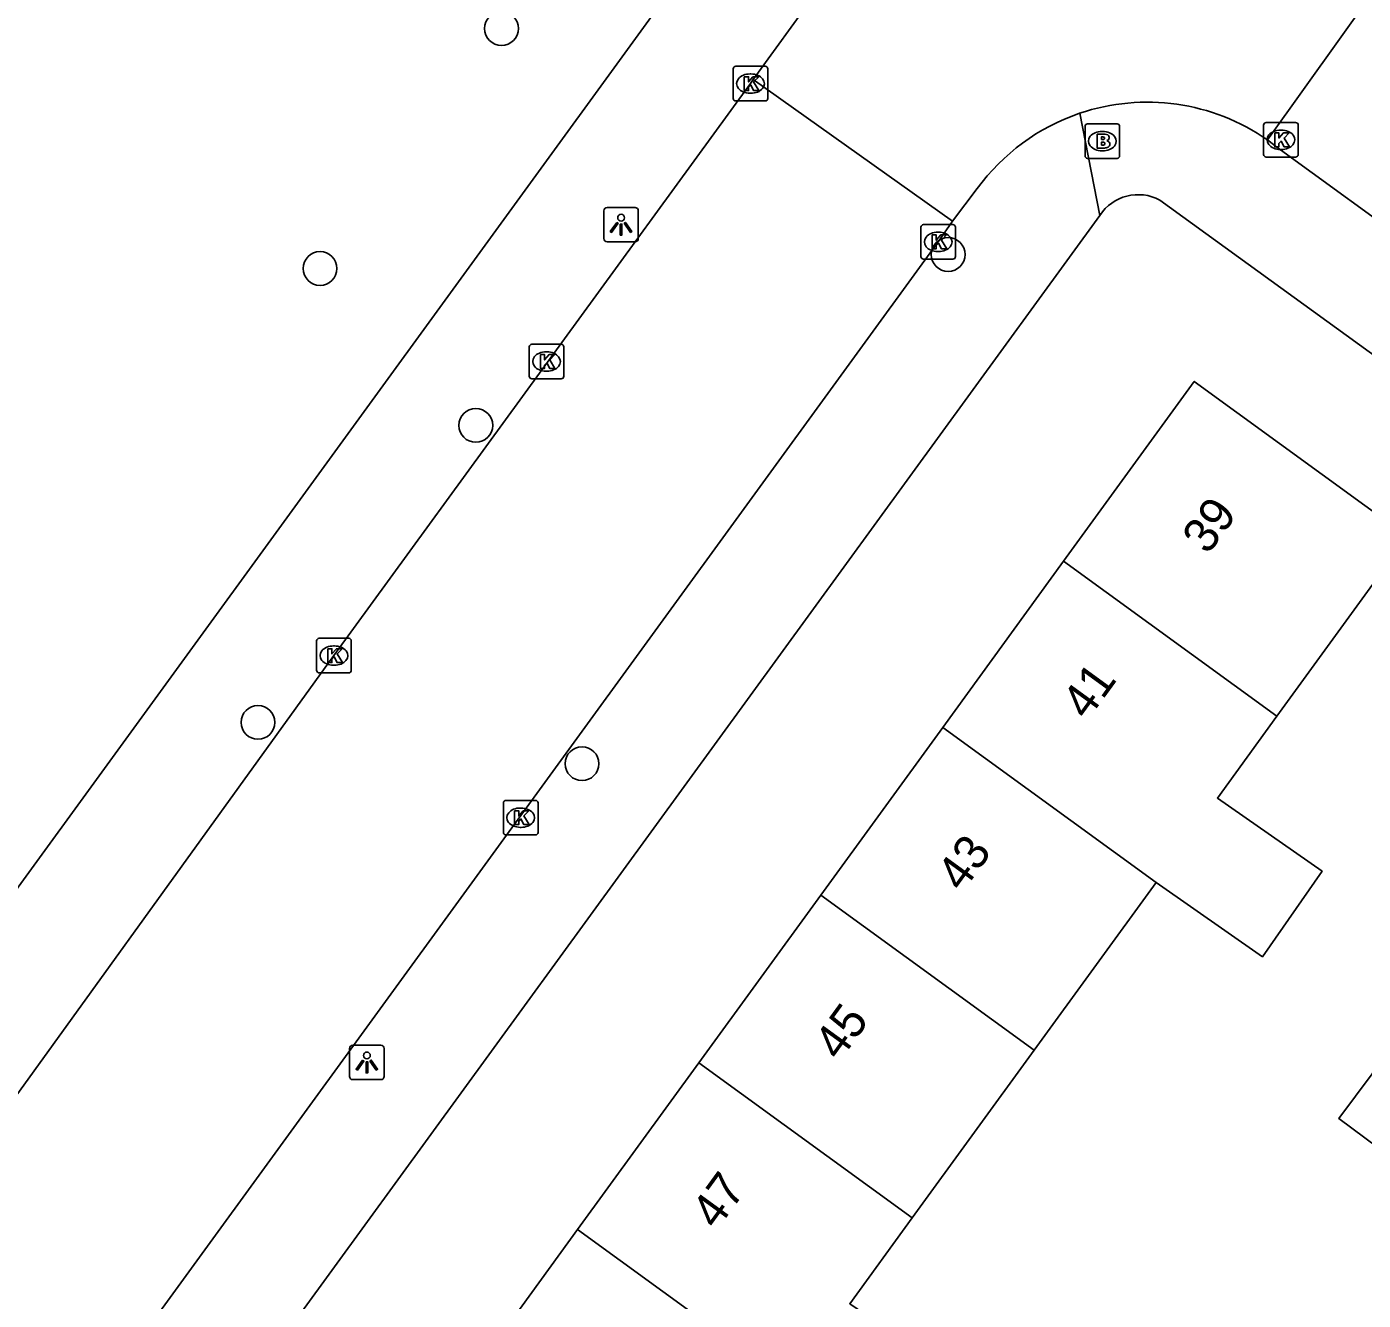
# Model space of a CAD drawing. Extents: x 159675 to 160530, y 382179 to 382901.
# Drawn here: x 160100.56 to 160139.21, y 382590.02 to 382626.86 of the extents above; entities that cross this region are included whole.
import ezdxf

# ---------------------------------------------------------------- set-up
doc = ezdxf.new("R2010")
doc.units = 0
for name, color, linetype in [('IMGEO_Boom', 7, 'Continuous'), ('IMGEO_Brandkraan', 7, 'Continuous'), ('IMGEO_Kolk', 7, 'Continuous'), ('IMGEO_Lichtpunt', 7, 'Continuous'), ('IMGEO_Pand', 7, 'Continuous'), ('IMGEO_Pand_nummerreeks', 7, 'Continuous'), ('IMGEO_Rijbaan_lokaal_open', 7, 'Continuous'), ('IMGEO_Voetpad_open', 7, 'Continuous')]:
    doc.layers.add(name, color=color, linetype=linetype)

msp = doc.modelspace()

# ---------------------------------------------------------------- linework, layer by layer
at = {"layer": 'IMGEO_Boom'}
for centre in [(160114.289, 382626.806), (160127.205, 382620.272), (160109.04, 382619.867), (160113.544, 382615.329), (160107.245, 382606.738), (160116.616, 382605.543)]:
    msp.add_circle(centre, 0.489, dxfattribs=at)
at = {"layer": 'IMGEO_Brandkraan'}
for p, q in [((160131.163, 382623.125), (160131.163, 382623.977)), ((160131.238, 382624.051), (160132.09, 382624.051)), ((160132.164, 382623.977), (160132.164, 382623.125)), ((160131.651, 382623.831), (160131.676, 382623.831)), ((160131.674, 382623.271), (160131.649, 382623.271)), ((160132.09, 382623.051), (160131.238, 382623.051))]:
    msp.add_line(p, q, dxfattribs=at)
for points in [[(160131.163, 382623.125), (160131.163, 382623.977)], [(160131.238, 382624.051), (160132.09, 382624.051)], [(160132.164, 382623.977), (160132.164, 382623.125)], [(160131.511, 382623.751), (160131.511, 382623.351), (160131.724, 382623.351)], [(160131.742, 382623.751), (160131.511, 382623.751)], [(160131.69, 382623.67), (160131.636, 382623.67), (160131.636, 382623.594)], [(160131.636, 382623.594), (160131.689, 382623.594)], [(160131.698, 382623.518), (160131.636, 382623.518), (160131.636, 382623.437)], [(160131.636, 382623.437), (160131.698, 382623.437)], [(160132.09, 382623.051), (160131.238, 382623.051)]]:
    msp.add_lwpolyline(points, dxfattribs=at)
for centre, radius, start, end in [((160131.24, 382623.975), 0.0765, 91.552, 178.448), ((160131.24, 382623.975), 0.0765, 91.552, 178.448), ((160132.088, 382623.975), 0.0765, 1.552, 88.448), ((160132.088, 382623.975), 0.0765, 1.552, 88.448), ((160131.691, 382623.632), 0.0379, 267.8285, 90.9355), ((160131.746, 382623.606), 0.145, 59.4692, 91.5367), ((160131.771, 382623.653), 0.0922, 285.5137, 58.1501), ((160131.699, 382623.477), 0.0404, 269.8759, 90.5077), ((160131.73, 382623.602), 0.251, 268.6676, 293.5347), ((160131.776, 382623.461), 0.105, 301.3115, 78.989), ((160131.24, 382623.127), 0.0765, 181.552, 268.448), ((160131.24, 382623.127), 0.0765, 181.552, 268.448), ((160132.088, 382623.127), 0.0765, 271.552, 358.448), ((160132.088, 382623.127), 0.0765, 271.552, 358.448)]:
    msp.add_arc(centre, radius, start, end, dxfattribs=at)
for centre, major_axis, ratio, start_param, end_param in [((160131.65, 382623.551), (-0.387, 0.002), 0.722429, 4.712389, 7.853982), ((160131.675, 382623.551), (-0.39, 0.002), 0.717154, 1.570796, 4.712389)]:
    msp.add_ellipse(centre, major_axis=major_axis, ratio=ratio, start_param=start_param, end_param=end_param, dxfattribs=at)
at = {"layer": 'IMGEO_Kolk'}
for p, q in [((160120.987, 382624.788), (160120.987, 382625.64)), ((160121.062, 382625.714), (160121.914, 382625.714)), ((160121.988, 382625.64), (160121.988, 382624.788)), ((160121.475, 382625.494), (160121.5, 382625.494)), ((160121.498, 382624.934), (160121.473, 382624.934)), ((160121.914, 382624.714), (160121.062, 382624.714)), ((160136.327, 382623.163), (160136.327, 382624.015)), ((160136.402, 382624.089), (160137.254, 382624.089)), ((160137.328, 382624.015), (160137.328, 382623.163)), ((160136.815, 382623.869), (160136.84, 382623.869)), ((160136.838, 382623.309), (160136.813, 382623.309)), ((160137.254, 382623.089), (160136.402, 382623.089)), ((160126.417, 382620.21), (160126.417, 382621.062)), ((160126.492, 382621.136), (160127.344, 382621.136)), ((160126.905, 382620.916), (160126.93, 382620.916)), ((160127.418, 382621.062), (160127.418, 382620.21)), ((160127.344, 382620.136), (160126.492, 382620.136)), ((160126.928, 382620.356), (160126.903, 382620.356)), ((160115.09, 382616.749), (160115.09, 382617.601)), ((160115.165, 382617.675), (160116.017, 382617.675)), ((160115.578, 382617.455), (160115.603, 382617.455)), ((160116.091, 382617.601), (160116.091, 382616.749)), ((160116.017, 382616.675), (160115.165, 382616.675)), ((160115.601, 382616.895), (160115.576, 382616.895)), ((160108.942, 382608.244), (160108.942, 382609.096)), ((160109.017, 382609.17), (160109.869, 382609.17)), ((160109.43, 382608.95), (160109.455, 382608.95)), ((160109.943, 382609.096), (160109.943, 382608.244)), ((160109.869, 382608.17), (160109.017, 382608.17)), ((160109.453, 382608.39), (160109.428, 382608.39)), ((160114.343, 382603.556), (160114.343, 382604.408)), ((160114.418, 382604.482), (160115.27, 382604.482)), ((160115.344, 382604.408), (160115.344, 382603.556)), ((160114.831, 382604.262), (160114.856, 382604.262)), ((160114.854, 382603.702), (160114.829, 382603.702)), ((160115.27, 382603.482), (160114.418, 382603.482))]:
    msp.add_line(p, q, dxfattribs=at)
for points in [[(160120.987, 382624.788), (160120.987, 382625.64)], [(160121.062, 382625.714), (160121.914, 382625.714)], [(160121.988, 382625.64), (160121.988, 382624.788)], [(160121.308, 382625.414), (160121.431, 382625.414), (160121.431, 382625.263), (160121.561, 382625.414), (160121.725, 382625.414), (160121.579, 382625.263), (160121.732, 382625.014), (160121.58, 382625.014), (160121.495, 382625.178), (160121.431, 382625.111), (160121.431, 382625.014), (160121.308, 382625.014), (160121.308, 382625.414)], [(160121.914, 382624.714), (160121.062, 382624.714)], [(160136.327, 382623.163), (160136.327, 382624.015)], [(160136.402, 382624.089), (160137.254, 382624.089)], [(160137.328, 382624.015), (160137.328, 382623.163)], [(160136.648, 382623.789), (160136.771, 382623.789), (160136.771, 382623.638), (160136.901, 382623.789), (160137.065, 382623.789), (160136.919, 382623.638), (160137.072, 382623.389), (160136.92, 382623.389), (160136.835, 382623.553), (160136.771, 382623.486), (160136.771, 382623.389), (160136.648, 382623.389), (160136.648, 382623.789)], [(160137.254, 382623.089), (160136.402, 382623.089)], [(160126.417, 382620.21), (160126.417, 382621.062)], [(160126.492, 382621.136), (160127.344, 382621.136)], [(160127.418, 382621.062), (160127.418, 382620.21)], [(160126.738, 382620.836), (160126.861, 382620.836), (160126.861, 382620.685), (160126.991, 382620.836), (160127.155, 382620.836), (160127.009, 382620.685), (160127.162, 382620.436), (160127.01, 382620.436), (160126.925, 382620.6), (160126.861, 382620.533), (160126.861, 382620.436), (160126.738, 382620.436), (160126.738, 382620.836)], [(160127.344, 382620.136), (160126.492, 382620.136)], [(160115.09, 382616.749), (160115.09, 382617.601)], [(160115.165, 382617.675), (160116.017, 382617.675)], [(160116.091, 382617.601), (160116.091, 382616.749)], [(160115.411, 382617.375), (160115.534, 382617.375), (160115.534, 382617.224), (160115.664, 382617.375), (160115.828, 382617.375), (160115.682, 382617.224), (160115.835, 382616.975), (160115.683, 382616.975), (160115.598, 382617.139), (160115.534, 382617.072), (160115.534, 382616.975), (160115.411, 382616.975), (160115.411, 382617.375)], [(160116.017, 382616.675), (160115.165, 382616.675)], [(160108.942, 382608.244), (160108.942, 382609.096)], [(160109.017, 382609.17), (160109.869, 382609.17)], [(160109.943, 382609.096), (160109.943, 382608.244)], [(160109.263, 382608.87), (160109.386, 382608.87), (160109.386, 382608.719), (160109.516, 382608.87), (160109.68, 382608.87), (160109.534, 382608.719), (160109.687, 382608.47), (160109.535, 382608.47), (160109.45, 382608.634), (160109.386, 382608.567), (160109.386, 382608.47), (160109.263, 382608.47), (160109.263, 382608.87)], [(160109.869, 382608.17), (160109.017, 382608.17)], [(160114.343, 382603.556), (160114.343, 382604.408)], [(160114.418, 382604.482), (160115.27, 382604.482)], [(160115.344, 382604.408), (160115.344, 382603.556)], [(160114.664, 382604.182), (160114.787, 382604.182), (160114.787, 382604.031), (160114.917, 382604.182), (160115.081, 382604.182), (160114.935, 382604.031), (160115.088, 382603.782), (160114.936, 382603.782), (160114.851, 382603.946), (160114.787, 382603.879), (160114.787, 382603.782), (160114.664, 382603.782), (160114.664, 382604.182)], [(160115.27, 382603.482), (160114.418, 382603.482)]]:
    msp.add_lwpolyline(points, dxfattribs=at)
for centre, start, end in [((160121.064, 382625.638), 91.552, 178.448), ((160121.064, 382625.638), 91.552, 178.448), ((160121.912, 382625.638), 1.552, 88.448), ((160121.912, 382625.638), 1.552, 88.448), ((160121.064, 382624.79), 181.552, 268.448), ((160121.064, 382624.79), 181.552, 268.448), ((160121.912, 382624.79), 271.552, 358.448), ((160121.912, 382624.79), 271.552, 358.448), ((160136.404, 382624.013), 91.552, 178.448), ((160136.404, 382624.013), 91.552, 178.448), ((160137.252, 382624.013), 1.552, 88.448), ((160137.252, 382624.013), 1.552, 88.448), ((160136.404, 382623.165), 181.552, 268.448), ((160136.404, 382623.165), 181.552, 268.448), ((160137.252, 382623.165), 271.552, 358.448), ((160137.252, 382623.165), 271.552, 358.448), ((160126.494, 382621.06), 91.552, 178.448), ((160126.494, 382621.06), 91.552, 178.448), ((160127.342, 382621.06), 1.552, 88.448), ((160127.342, 382621.06), 1.552, 88.448), ((160126.494, 382620.212), 181.552, 268.448), ((160126.494, 382620.212), 181.552, 268.448), ((160127.342, 382620.212), 271.552, 358.448), ((160127.342, 382620.212), 271.552, 358.448), ((160115.167, 382617.599), 91.552, 178.448), ((160115.167, 382617.599), 91.552, 178.448), ((160116.015, 382617.599), 1.552, 88.448), ((160116.015, 382617.599), 1.552, 88.448), ((160115.167, 382616.751), 181.552, 268.448), ((160115.167, 382616.751), 181.552, 268.448), ((160116.015, 382616.751), 271.552, 358.448), ((160116.015, 382616.751), 271.552, 358.448), ((160109.019, 382609.094), 91.552, 178.448), ((160109.019, 382609.094), 91.552, 178.448), ((160109.867, 382609.094), 1.552, 88.448), ((160109.867, 382609.094), 1.552, 88.448), ((160109.019, 382608.246), 181.552, 268.448), ((160109.019, 382608.246), 181.552, 268.448), ((160109.867, 382608.246), 271.552, 358.448), ((160109.867, 382608.246), 271.552, 358.448), ((160114.42, 382604.406), 91.552, 178.448), ((160114.42, 382604.406), 91.552, 178.448), ((160115.268, 382604.406), 1.552, 88.448), ((160115.268, 382604.406), 1.552, 88.448), ((160114.42, 382603.558), 181.552, 268.448), ((160114.42, 382603.558), 181.552, 268.448), ((160115.268, 382603.558), 271.552, 358.448), ((160115.268, 382603.558), 271.552, 358.448)]:
    msp.add_arc(centre, 0.0765, start, end, dxfattribs=at)
for centre, major_axis, ratio, start_param, end_param in [((160121.474, 382625.214), (-0.387, 0.002), 0.722429, 4.712389, 7.853982), ((160121.499, 382625.214), (-0.39, 0.002), 0.717154, 1.570796, 4.712389), ((160136.814, 382623.589), (-0.387, 0.002), 0.722429, 4.712389, 7.853982), ((160136.839, 382623.589), (-0.39, 0.002), 0.717154, 1.570796, 4.712389), ((160126.904, 382620.636), (-0.387, 0.002), 0.722429, 4.712389, 7.853982), ((160126.929, 382620.636), (-0.39, 0.002), 0.717154, 1.570796, 4.712389), ((160115.577, 382617.175), (-0.387, 0.002), 0.722429, 4.712389, 7.853982), ((160115.602, 382617.175), (-0.39, 0.002), 0.717154, 1.570796, 4.712389), ((160109.429, 382608.67), (-0.387, 0.002), 0.722429, 4.712389, 7.853982), ((160109.454, 382608.67), (-0.39, 0.002), 0.717154, 1.570796, 4.712389), ((160114.83, 382603.982), (-0.387, 0.002), 0.722429, 4.712389, 7.853982), ((160114.855, 382603.982), (-0.39, 0.002), 0.717154, 1.570796, 4.712389)]:
    msp.add_ellipse(centre, major_axis=major_axis, ratio=ratio, start_param=start_param, end_param=end_param, dxfattribs=at)
at = {"layer": 'IMGEO_Lichtpunt'}
for p, q in [((160117.248, 382621.537), (160117.248, 382620.73)), ((160117.248, 382621.537), (160117.248, 382620.73)), ((160118.15, 382621.632), (160117.342, 382621.632)), ((160118.15, 382621.632), (160117.342, 382621.632)), ((160118.244, 382620.73), (160118.244, 382621.537)), ((160118.244, 382620.73), (160118.244, 382621.537)), ((160117.342, 382620.636), (160118.15, 382620.636)), ((160117.342, 382620.636), (160118.15, 382620.636)), ((160109.895, 382597.307), (160109.895, 382596.5)), ((160109.895, 382597.307), (160109.895, 382596.5)), ((160110.797, 382597.402), (160109.989, 382597.402)), ((160110.797, 382597.402), (160109.989, 382597.402)), ((160110.891, 382596.5), (160110.891, 382597.307)), ((160110.891, 382596.5), (160110.891, 382597.307)), ((160109.989, 382596.406), (160110.797, 382596.406)), ((160109.989, 382596.406), (160110.797, 382596.406))]:
    msp.add_line(p, q, dxfattribs=at)
for points in [[(160117.622, 382621.201), (160117.661, 382621.173), (160117.473, 382620.911), (160117.435, 382620.938), (160117.622, 382621.201)], [(160117.724, 382621.153), (160117.771, 382621.153), (160117.771, 382620.831), (160117.724, 382620.831), (160117.724, 382621.153)], [(160117.834, 382621.173), (160117.872, 382621.2), (160118.059, 382620.938), (160118.02, 382620.91), (160117.834, 382621.173)], [(160110.269, 382596.971), (160110.308, 382596.943), (160110.12, 382596.681), (160110.082, 382596.708), (160110.269, 382596.971)], [(160110.371, 382596.923), (160110.418, 382596.923), (160110.418, 382596.601), (160110.371, 382596.601), (160110.371, 382596.923)], [(160110.481, 382596.943), (160110.519, 382596.97), (160110.706, 382596.708), (160110.667, 382596.68), (160110.481, 382596.943)]]:
    msp.add_lwpolyline(points, dxfattribs=at)
for centre in [(160117.747, 382621.335), (160110.394, 382597.105)]:
    msp.add_circle(centre, 0.0994, dxfattribs=at)
for centre, start, end in [((160117.342, 382621.537), 90, 180), ((160117.342, 382621.537), 90, 180), ((160118.15, 382621.537), 0, 90), ((160118.15, 382621.537), 0, 90), ((160117.342, 382620.73), 180, 270), ((160117.342, 382620.73), 180, 270), ((160118.15, 382620.73), 270, 0), ((160118.15, 382620.73), 270, 360), ((160109.989, 382597.307), 90, 180), ((160109.989, 382597.307), 90, 180), ((160110.797, 382597.307), 0, 90), ((160110.797, 382597.307), 0, 90), ((160109.989, 382596.5), 180, 270), ((160109.989, 382596.5), 180, 270), ((160110.797, 382596.5), 270, 0), ((160110.797, 382596.5), 270, 360)]:
    msp.add_arc(centre, 0.0946, start, end, dxfattribs=at)
at = {"layer": 'IMGEO_Pand'}
for points in [[(160130.542, 382611.402), (160134.322, 382616.601), (160140.492, 382612.116), (160136.713, 382606.917)], [(160127.047, 382606.593), (160130.542, 382611.402)], [(160136.713, 382606.917), (160130.542, 382611.402)], [(160123.52, 382601.741), (160127.047, 382606.593)], [(160127.047, 382606.593), (160133.217, 382602.109)], [(160136.713, 382606.917), (160134.991, 382604.549), (160138.019, 382602.434), (160136.291, 382599.961), (160133.217, 382602.109)], [(160133.217, 382602.109), (160129.69, 382597.257)], [(160119.993, 382596.889), (160123.52, 382601.741)], [(160129.69, 382597.257), (160123.52, 382601.741)], [(160129.69, 382597.257), (160126.162, 382592.404)], [(160139.948, 382597.218), (160138.506, 382595.279), (160143.351, 382591.675)], [(160116.488, 382592.067), (160119.993, 382596.889)], [(160119.993, 382596.889), (160126.162, 382592.404)], [(160126.162, 382592.404), (160124.357, 382589.921), (160126.478, 382588.471), (160124.848, 382586.086), (160122.658, 382587.583)], [(160116.488, 382592.067), (160112.925, 382587.167)], [(160122.658, 382587.583), (160116.488, 382592.067)]]:
    msp.add_lwpolyline(points, dxfattribs=at)
at = {"layer": 'IMGEO_Rijbaan_lokaal_open'}
for points in [[(160133.916, 382642.352), (160121.569, 382625.329)], [(160140.555, 382629.351), (160136.439, 382623.587)], [(160121.569, 382625.329), (160121.488, 382625.214), (160109.443, 382608.67), (160097.463, 382592.089), (160084.229, 382573.928), (160076.311, 382563.035), (160076.064, 382562.694)], [(160121.569, 382625.329), (160127.333, 382621.232)], [(160136.439, 382623.587), (160136.712, 382623.379), (160240.412, 382548.029)], [(160128.048, 382622.176), (160127.333, 382621.232)], [(160127.333, 382621.232), (160126.918, 382620.636), (160102.443, 382586.988)]]:
    msp.add_lwpolyline(points, dxfattribs=at)
for centre, radius, start, end in [((160132.963, 382618.596), 6.082, 55.148, 108.7542), ((160132.956, 382618.609), 6.068, 108.7276, 143.9896)]:
    msp.add_arc(centre, radius, start, end, dxfattribs=at)
at = {"layer": 'IMGEO_Voetpad_open'}
for points in [[(160073.24, 382564.766), (160078.977, 382572.654), (160139.025, 382655.211)], [(160131.008, 382624.355), (160131.588, 382621.403)], [(160154.437, 382606.506), (160154.426, 382606.548), (160133.33, 382621.844)], [(160131.588, 382621.403), (160103.888, 382583.337)]]:
    msp.add_lwpolyline(points, dxfattribs=at)
msp.add_arc((160132.7, 382620.672), 1.33, 61.7224, 146.6903, dxfattribs=at)

# ---------------------------------------------------------------- texts
at = {"layer": 'IMGEO_Pand_nummerreeks'}
for s, p in [('39', (160134.715, 382611.562)), ('41', (160131.231, 382606.77)), ('43', (160127.615, 382601.796)), ('45', (160124.066, 382596.913)), ('47', (160120.516, 382592.03))]:
    msp.add_text(s, height=1, rotation=53.9854, dxfattribs=at).set_placement(p)

doc.saveas('drawing.dxf')
